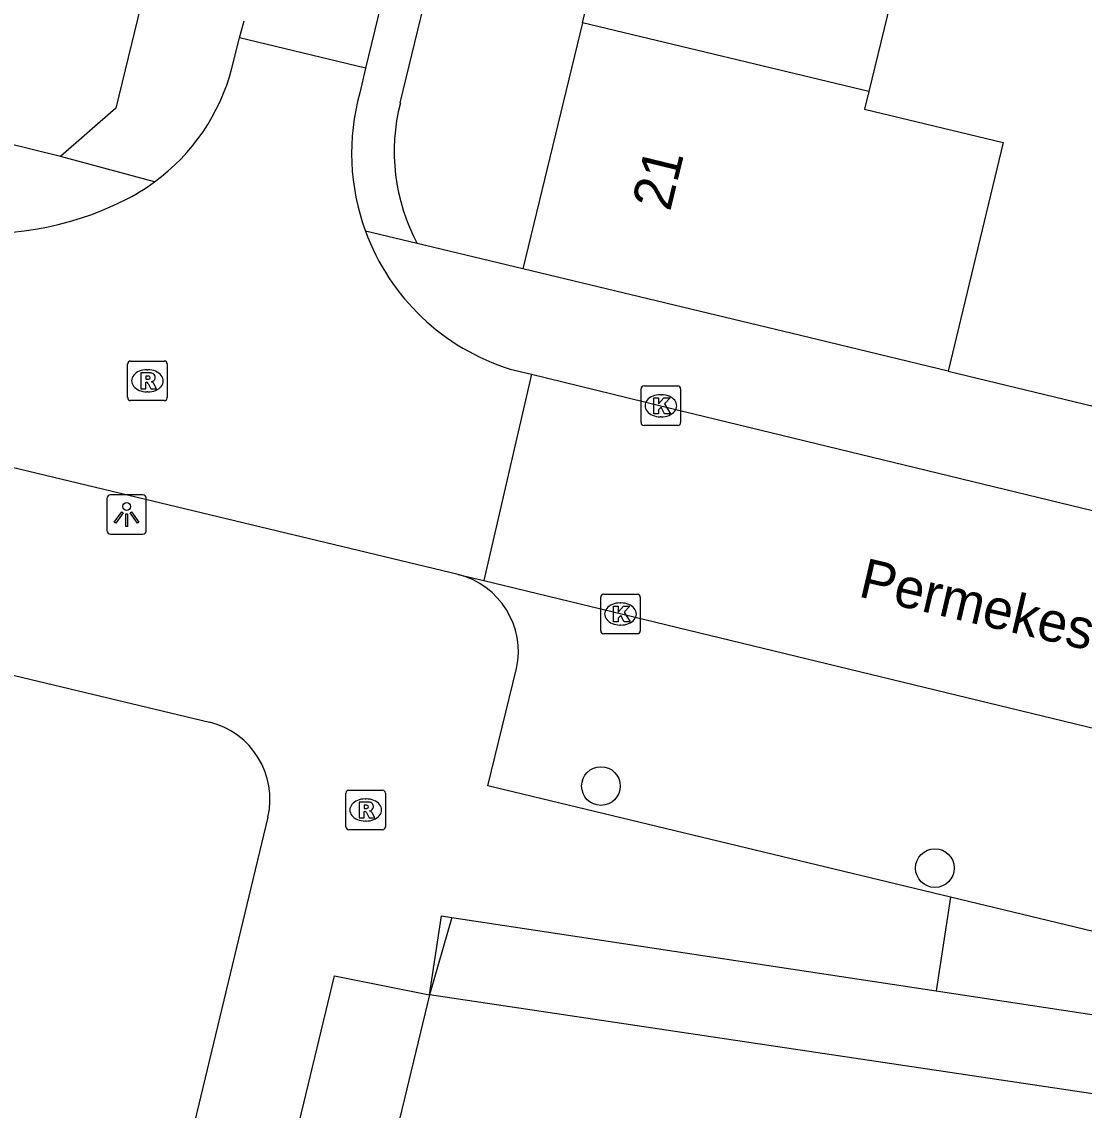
# Model space of a CAD drawing. Extents: x 162812 to 163818, y 381639 to 382470.
# Drawn here: x 163316.1 to 163342.98, y 382176.57 to 382204.11 of the extents above; entities that cross this region are included whole.
import ezdxf

# ---------------------------------------------------------------- set-up
doc = ezdxf.new("R2010")
doc.units = 0
for name, color, linetype in [('IMGEO_Boom', 7, 'Continuous'), ('IMGEO_Kolk', 7, 'Continuous'), ('IMGEO_Lichtpunt', 7, 'Continuous'), ('IMGEO_Openbare_ruimte_label', 7, 'Continuous'), ('IMGEO_Pand', 7, 'Continuous'), ('IMGEO_Pand_nummerreeks', 7, 'Continuous'), ('IMGEO_Rijbaan_lokaal_open', 7, 'Continuous'), ('IMGEO_Rioolput', 7, 'Continuous'), ('IMGEO_Voetpad_open', 7, 'Continuous')]:
    doc.layers.add(name, color=color, linetype=linetype)

msp = doc.modelspace()

# ---------------------------------------------------------------- linework, layer by layer
at = {"layer": 'IMGEO_Boom'}
for centre in [(163330.756, 382184.773), (163339.205, 382182.696)]:
    msp.add_circle(centre, 0.489, dxfattribs=at)
at = {"layer": 'IMGEO_Kolk'}
for p, q in [((163331.771, 382193.966), (163331.771, 382194.818)), ((163331.846, 382194.892), (163332.698, 382194.892)), ((163332.772, 382194.818), (163332.772, 382193.966)), ((163332.259, 382194.672), (163332.284, 382194.672)), ((163332.282, 382194.112), (163332.257, 382194.112)), ((163332.698, 382193.892), (163331.846, 382193.892)), ((163330.825, 382189.625), (163331.677, 382189.625)), ((163330.75, 382188.699), (163330.75, 382189.551)), ((163331.238, 382189.405), (163331.263, 382189.405)), ((163331.751, 382189.551), (163331.751, 382188.699)), ((163331.261, 382188.845), (163331.236, 382188.845)), ((163331.677, 382188.625), (163330.825, 382188.625))]:
    msp.add_line(p, q, dxfattribs=at)
for points in [[(163331.771, 382193.966), (163331.771, 382194.818)], [(163331.846, 382194.892), (163332.698, 382194.892)], [(163332.772, 382194.818), (163332.772, 382193.966)], [(163332.092, 382194.592), (163332.215, 382194.592), (163332.215, 382194.441), (163332.345, 382194.592), (163332.509, 382194.592), (163332.363, 382194.441), (163332.516, 382194.192), (163332.364, 382194.192), (163332.279, 382194.356), (163332.215, 382194.289), (163332.215, 382194.192), (163332.092, 382194.192), (163332.092, 382194.592)], [(163332.698, 382193.892), (163331.846, 382193.892)], [(163330.825, 382189.625), (163331.677, 382189.625)], [(163330.75, 382188.699), (163330.75, 382189.551)], [(163331.071, 382189.325), (163331.194, 382189.325), (163331.194, 382189.174), (163331.324, 382189.325), (163331.488, 382189.325), (163331.342, 382189.174), (163331.495, 382188.925), (163331.343, 382188.925), (163331.258, 382189.089), (163331.194, 382189.022), (163331.194, 382188.925), (163331.071, 382188.925), (163331.071, 382189.325)], [(163331.751, 382189.551), (163331.751, 382188.699)], [(163331.677, 382188.625), (163330.825, 382188.625)]]:
    msp.add_lwpolyline(points, dxfattribs=at)
for centre, start, end in [((163331.848, 382194.816), 91.552, 178.448), ((163331.848, 382194.816), 91.552, 178.448), ((163332.696, 382194.816), 1.552, 88.448), ((163332.696, 382194.816), 1.552, 88.448), ((163331.848, 382193.968), 181.552, 268.448), ((163331.848, 382193.968), 181.552, 268.448), ((163332.696, 382193.968), 271.552, 358.448), ((163332.696, 382193.968), 271.552, 358.448), ((163330.827, 382189.549), 91.552, 178.448), ((163330.827, 382189.549), 91.552, 178.448), ((163331.675, 382189.549), 1.552, 88.448), ((163331.675, 382189.549), 1.552, 88.448), ((163330.827, 382188.701), 181.552, 268.448), ((163330.827, 382188.701), 181.552, 268.448), ((163331.675, 382188.701), 271.552, 358.448), ((163331.675, 382188.701), 271.552, 358.448)]:
    msp.add_arc(centre, 0.0765, start, end, dxfattribs=at)
for centre, major_axis, ratio, start_param, end_param in [((163332.258, 382194.392), (-0.387, 0.002), 0.722429, 4.712389, 7.853982), ((163332.283, 382194.392), (-0.39, 0.002), 0.717154, 1.570796, 4.712389), ((163331.237, 382189.125), (-0.387, 0.002), 0.722429, 4.712389, 7.853982), ((163331.262, 382189.125), (-0.39, 0.002), 0.717154, 1.570796, 4.712389)]:
    msp.add_ellipse(centre, major_axis=major_axis, ratio=ratio, start_param=start_param, end_param=end_param, dxfattribs=at)
at = {"layer": 'IMGEO_Lichtpunt'}
for p, q in [((163319.159, 382192.141), (163318.351, 382192.141)), ((163319.159, 382192.141), (163318.351, 382192.141)), ((163318.257, 382192.046), (163318.257, 382191.239)), ((163318.257, 382192.046), (163318.257, 382191.239)), ((163319.253, 382191.239), (163319.253, 382192.046)), ((163319.253, 382191.239), (163319.253, 382192.046)), ((163318.351, 382191.145), (163319.159, 382191.145)), ((163318.351, 382191.145), (163319.159, 382191.145))]:
    msp.add_line(p, q, dxfattribs=at)
for points in [[(163318.631, 382191.71), (163318.67, 382191.682), (163318.482, 382191.42), (163318.444, 382191.447), (163318.631, 382191.71)], [(163318.733, 382191.662), (163318.78, 382191.662), (163318.78, 382191.34), (163318.733, 382191.34), (163318.733, 382191.662)], [(163318.843, 382191.682), (163318.881, 382191.709), (163319.068, 382191.447), (163319.029, 382191.419), (163318.843, 382191.682)]]:
    msp.add_lwpolyline(points, dxfattribs=at)
msp.add_circle((163318.756, 382191.844), 0.0994, dxfattribs=at)
for centre, start, end in [((163318.351, 382192.046), 90, 180), ((163318.351, 382192.046), 90, 180), ((163319.159, 382192.046), 0, 90), ((163319.159, 382192.046), 0, 90), ((163318.351, 382191.239), 180, 270), ((163318.351, 382191.239), 180, 270), ((163319.159, 382191.239), 270, 0), ((163319.159, 382191.239), 270, 360)]:
    msp.add_arc(centre, 0.0946, start, end, dxfattribs=at)
at = {"layer": 'IMGEO_Pand'}
for points in [[(163330.293, 382204.079), (163331.674, 382209.763)], [(163338.915, 382208.03), (163337.533, 382202.345)], [(163330.293, 382204.079), (163328.78, 382197.856)], [(163337.533, 382202.345), (163330.293, 382204.079)], [(163337.533, 382202.345), (163337.424, 382201.894), (163340.929, 382201.052), (163339.539, 382195.27)], [(163339.539, 382195.27), (163336.019, 382196.116), (163328.78, 382197.856)], [(163326.422, 382179.494), (163323.822, 382168.72)], [(163354.552, 382177.262), (163354.506, 382176.952), (163354.718, 382176.939), (163354.444, 382175.305), (163326.422, 382179.494)]]:
    msp.add_lwpolyline(points, dxfattribs=at)
at = {"layer": 'IMGEO_Rijbaan_lokaal_open'}
for points in [[(163339.145, 382262.043), (163339.056, 382261.643), (163336.233, 382250), (163331.974, 382232.436), (163324.797, 382202.931)], [(163321.609, 382203.703), (163321.731, 382204.132)], [(163321.42, 382202.929), (163321.609, 382203.703)], [(163324.797, 382202.931), (163321.609, 382203.703)], [(163324.797, 382202.931), (163324.654, 382202.308)], [(163329, 382195.189), (163327.797, 382189.969)], [(163328.462, 382195.318), (163329, 382195.189)], [(163329, 382195.189), (163332.269, 382194.391), (163351.09, 382189.825), (163354.761, 382188.944), (163360.986, 382187.423), (163363.371, 382186.849)], [(163327.147, 382190.126), (163311.244, 382193.937)], [(163327.147, 382190.126), (163327.797, 382189.969)], [(163327.797, 382189.969), (163354.425, 382183.525)]]:
    msp.add_lwpolyline(points, dxfattribs=at)
for centre, radius, start, end in [((163316.381, 382204.258), 5.211, 306.2415, 345.2269), ((163330.171, 382200.783), 5.724, 164.5471, 200.1962), ((163316.343, 382204.324), 5.288, 296.2944, 306.1522), ((163315.148, 382206.654), 7.905, 262.4033, 296.5781), ((163330.171, 382200.779), 5.723, 200.1624, 252.6249)]:
    msp.add_arc(centre, radius, start, end, dxfattribs=at)
at = {"layer": 'IMGEO_Rioolput'}
for p, q in [((163318.781, 382194.597), (163318.781, 382195.449)), ((163318.856, 382195.523), (163319.708, 382195.523)), ((163319.782, 382195.449), (163319.782, 382194.597)), ((163319.269, 382195.303), (163319.294, 382195.303)), ((163319.292, 382194.743), (163319.267, 382194.743)), ((163319.708, 382194.523), (163318.856, 382194.523)), ((163324.378, 382184.667), (163325.23, 382184.667)), ((163324.303, 382183.741), (163324.303, 382184.593)), ((163324.791, 382184.447), (163324.816, 382184.447)), ((163325.304, 382184.593), (163325.304, 382183.741)), ((163324.814, 382183.887), (163324.789, 382183.887)), ((163325.23, 382183.667), (163324.378, 382183.667))]:
    msp.add_line(p, q, dxfattribs=at)
for points in [[(163318.781, 382194.597), (163318.781, 382195.449)], [(163318.856, 382195.523), (163319.708, 382195.523)], [(163319.782, 382195.449), (163319.782, 382194.597)], [(163319.37, 382195.221), (163319.118, 382195.223), (163319.118, 382194.823)], [(163319.296, 382195.142), (163319.242, 382195.142), (163319.242, 382195.061)], [(163319.118, 382194.823), (163319.242, 382194.823), (163319.242, 382194.985), (163319.253, 382194.985)], [(163319.242, 382195.061), (163319.294, 382195.061)], [(163319.3, 382194.956), (163319.371, 382194.823), (163319.511, 382194.823), (163319.446, 382194.949)], [(163319.708, 382194.523), (163318.856, 382194.523)], [(163324.378, 382184.667), (163325.23, 382184.667)], [(163324.303, 382183.741), (163324.303, 382184.593)], [(163324.892, 382184.365), (163324.64, 382184.367), (163324.64, 382183.967)], [(163325.304, 382184.593), (163325.304, 382183.741)], [(163324.64, 382183.967), (163324.764, 382183.967), (163324.764, 382184.129), (163324.775, 382184.129)], [(163324.818, 382184.286), (163324.764, 382184.286), (163324.764, 382184.205)], [(163324.764, 382184.205), (163324.816, 382184.205)], [(163324.822, 382184.1), (163324.893, 382183.967), (163325.033, 382183.967), (163324.968, 382184.093)], [(163325.23, 382183.667), (163324.378, 382183.667)]]:
    msp.add_lwpolyline(points, dxfattribs=at)
for centre, radius, start, end in [((163318.858, 382195.447), 0.0765, 91.552, 178.448), ((163318.858, 382195.447), 0.0765, 91.552, 178.448), ((163319.706, 382195.447), 0.0765, 1.552, 88.448), ((163319.706, 382195.447), 0.0765, 1.552, 88.448), ((163319.302, 382195.046), 0.0964, 77.0061, 93.1865), ((163319.316, 382195.103), 0.0378, 276.6634, 79.6772), ((163319.369, 382195.111), 0.109, 350.3612, 89.416), ((163319.367, 382195.111), 0.112, 277.5842, 350.9817), ((163319.252, 382194.932), 0.0533, 26.0293, 88.6989), ((163319.278, 382195.25), 0.19, 274.7715, 282.9687), ((163319.351, 382194.896), 0.108, 29.5134, 73.7905), ((163318.858, 382194.599), 0.0765, 181.552, 268.448), ((163318.858, 382194.599), 0.0765, 181.552, 268.448), ((163319.706, 382194.599), 0.0765, 271.552, 358.448), ((163319.706, 382194.599), 0.0765, 271.552, 358.448), ((163324.38, 382184.591), 0.0765, 91.552, 178.448), ((163324.38, 382184.591), 0.0765, 91.552, 178.448), ((163325.228, 382184.591), 0.0765, 1.552, 88.448), ((163325.228, 382184.591), 0.0765, 1.552, 88.448), ((163324.891, 382184.255), 0.109, 350.3612, 89.416), ((163324.774, 382184.076), 0.0533, 26.0293, 88.6989), ((163324.8, 382184.394), 0.19, 274.7715, 282.9687), ((163324.824, 382184.19), 0.0964, 77.0061, 93.1865), ((163324.838, 382184.247), 0.0378, 276.6634, 79.6772), ((163324.889, 382184.255), 0.112, 277.5842, 350.9817), ((163324.873, 382184.04), 0.108, 29.5134, 73.7905), ((163324.38, 382183.743), 0.0765, 181.552, 268.448), ((163324.38, 382183.743), 0.0765, 181.552, 268.448), ((163325.228, 382183.743), 0.0765, 271.552, 358.448), ((163325.228, 382183.743), 0.0765, 271.552, 358.448)]:
    msp.add_arc(centre, radius, start, end, dxfattribs=at)
for centre, major_axis, ratio, start_param, end_param in [((163319.268, 382195.023), (-0.387, 0.002), 0.722429, 4.712389, 7.853982), ((163319.293, 382195.023), (-0.39, 0.002), 0.717154, 1.570796, 4.712389), ((163324.79, 382184.167), (-0.387, 0.002), 0.722429, 4.712389, 7.853982), ((163324.815, 382184.167), (-0.39, 0.002), 0.717154, 1.570796, 4.712389)]:
    msp.add_ellipse(centre, major_axis=major_axis, ratio=ratio, start_param=start_param, end_param=end_param, dxfattribs=at)
at = {"layer": 'IMGEO_Voetpad_open'}
for points in [[(163329.707, 382265.204), (163333.628, 382264.215), (163330.176, 382250), (163326.205, 382233.651), (163318.48, 382201.917), (163317.086, 382200.697)], [(163325.68, 382202.052), (163332.984, 382232.131), (163337.307, 382250), (163340.354, 382262.596), (163344.289, 382261.664)], [(163317.086, 382200.697), (163314.205, 382201.406)], [(163319.462, 382200.055), (163317.086, 382200.697)], [(163326.109, 382198.494), (163324.799, 382198.807)], [(163328.78, 382197.856), (163326.109, 382198.494)], [(163339.539, 382195.27), (163346.423, 382193.603)], [(163314.533, 382187.899), (163320.851, 382186.391)], [(163339.6, 382181.962), (163327.891, 382184.78), (163328.623, 382187.748)], [(163322.331, 382183.982), (163318.73, 382169.011), (163308.573, 382171.509), (163312.197, 382186.407)], [(163352.032, 382182.189), (163351.308, 382179.144), (163339.6, 382181.962)], [(163339.6, 382181.962), (163339.239, 382179.588)], [(163326.422, 382179.494), (163326.722, 382181.493), (163326.986, 382181.449)], [(163326.986, 382181.449), (163326.422, 382179.494)], [(163326.986, 382181.449), (163339.239, 382179.588)], [(163320.628, 382165.9), (163324.015, 382179.968), (163326.422, 382179.494)], [(163339.239, 382179.588), (163354.552, 382177.262)]]:
    msp.add_lwpolyline(points, dxfattribs=at)
for centre, radius, start, end in [((163330.459, 382200.823), 4.934, 165.58, 208.1703), ((163326.644, 382188.167), 2.023, 348.051, 75.6039), ((163320.367, 382184.435), 2.015, 347.0241, 76.1059)]:
    msp.add_arc(centre, radius, start, end, dxfattribs=at)

# ---------------------------------------------------------------- texts
at = {"layer": 'IMGEO_Openbare_ruimte_label'}
msp.add_text('Permekestraat', height=1, rotation=346.8251, dxfattribs=at).set_placement((163337.241, 382189.573))
at = {"layer": 'IMGEO_Pand_nummerreeks'}
msp.add_text('21', height=1, rotation=76.3409, dxfattribs=at).set_placement((163332.504, 382199.288))

doc.saveas('drawing.dxf')
